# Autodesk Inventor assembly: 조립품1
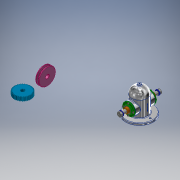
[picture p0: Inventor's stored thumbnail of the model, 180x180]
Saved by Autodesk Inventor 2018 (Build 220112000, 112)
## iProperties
Created: 2019-11
Part Number: 조립품1
Material: 일반
Document SubType Name: Assembly
Designer: CAD
Author: CAD
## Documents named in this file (14)
- C:\Users\CAD\Desktop\491104V1042\조립품1.iam
- C:\Users\CAD\Desktop\491104V1042\본체.ipt
- C:\Users\CAD\Desktop\491104V1042\볼트 M4.ipt
- C:\Users\CAD\Desktop\491104V1042\부시.ipt
- C:\Users\CAD\Desktop\491104V1042\스퍼기어.ipt
- C:\Users\CAD\Desktop\491104V1042\오일 실 26 38 8.ipt
- C:\Users\CAD\Desktop\491104V1042\와셔 12x24.ipt
- C:\Users\CAD\Desktop\491104V1042\축.ipt
- C:\Users\CAD\Desktop\491104V1042\커버.ipt
- C:\Users\CAD\Desktop\491104V1042\키 5x5x12.ipt
- C:\Users\CAD\Desktop\491104V1042\V-벨트풀리.ipt
- V-벨트풀리.ipt
- C:\Users\CAD\Desktop\491104V1042\너트 M12x1.25.ipt
- C:\Users\CAD\Desktop\491104V1042\베어링 6203.ipt
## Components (1 placed, 1 different names)
1. V-벨트풀리:1
## Named parameters: d41_d39 = 0, d42_d40 = 0
